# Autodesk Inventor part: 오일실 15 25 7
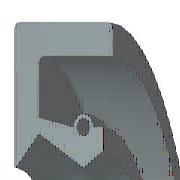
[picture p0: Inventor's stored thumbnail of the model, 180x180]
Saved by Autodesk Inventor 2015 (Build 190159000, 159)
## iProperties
Created: 2012-02
Part Number: 오일실 15 25 7
Material: 고무
Description: 오일-실
Document SubType Name: Modeling
Standard: KS B 2804
Designer: mduedu
Standards Organization: KS
Language: ko-KR
Size Designation: D - 15 25 7
Categories: <MemberInstance><Categories><Category DisplayName="샤프트 부품" InternalName="7f7aeb1f-a693-4053-b835-cee3144e0d98" Mnemonic="SHFT"><Category DisplayName="실링" Intern
Density: 0.93 g/cm^3
Appearance: 고무 - 검은색 - 버전 1.1
IsCustomPart: 1
Author: mduedu
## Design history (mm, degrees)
revolve "본체" stored, may be unused: angle "d17" = 90 deg
revolve "스프링1" stored, may be unused: angle "d18" = 90 deg
body "Solid1"
sketch "스케치1"
  geometry: L1 (0, 12.5)-(7, 12.5); L2 (7, 10.75)-(1.75, 10.75); L3 (1.75, 9.25)-(4.9, 7.5); L4 (4.9, 7.5)-(0, 7.5); L5 (0, 0)-(9.586, 0) reference; L6 (4.9, 7.5)-(6.3, 8.375); L7 (0, 18)-(0, -3) reference; L8 (-1.941, 0)-(11.507, 0) reference; L9 (4.2, 9.6)-(1.75, 10.09); L10 (1.75, 10.09)-(1.75, 10.75); L11 (0, 12.5)-(0, 7.588); L12 (4.9, 7.5)-(0, 7.5); L13 (1.75, 9.25)-(0.152, 7.528); L14 (7, 12.5)-(7, 10.75); L15 (5.6, 9.6)-(6.3, 9.6); L16 (6.3, 9.6)-(6.3, 8.375); C1 r 0.455 at (4.9, 9.6); A1 r 0.7 centre (4.9, 9.6) between (5.6, 9.6) and (4.2, 9.6); A2 r 0.088 centre (0.088, 7.588) between (0, 7.588) and (0.152, 7.528); 1 further point
  constraints: 28 end point, 5 horizontal alignment, 5 point on line, 4 point on circle, 4 vertical alignment, 3 centre point, 3 tangent, 2 collinear, 2 horizontal, 2 perpendicular, 1 coincident, 1 parallel
  dimensions: "d0" = 25 diameter of L1 L5 (= SD2); "d1" = 1.75 distance of L1.end L2.start (= SD); "d2" = 0.91 diameter of C1 (= SPDI); "d3" = 1.4 diameter of A1 (= SPDA); "d4" = 15 diameter of L3.end L5 (= NND); "d5" = 18.5 diameter of L3.start L5 (= TKDM); "d7" = 20.18 diameter of L9.end L5 (= TKDM + 0.24 x SWDT); "d8" = 1.75 distance between parallel lines of L11 L10 (= SD); "d9" = 4.9 distance from line of L11 C1.centre (= SPDST); "d10" = 19.2 diameter of C1.centre L5 (= HLDM); "d11" = 0.0875 radius of A2 (= 0.25 x LAB); "d12" = 6.3 distance between parallel lines of L11 L16 (= SDI); "d13" = 16.75 diameter of L6.end L5 (= ABDM); "d14" = 7 distance from line of L11 L1.end (= SWDT)
fillet "모깎기1" dims "d6" = 0.3 (= RR)
other parameters: "SD2" = 25 [user parameter; used in 1 equation term], "SWDT" = 7 [user parameter; used in 2 equation terms], "RR" = 0.3 [user parameter; used in 1 equation term], "SD" = 1.75 [user parameter; used in 2 equation terms], "NND" = 15 [user parameter; used in 1 equation term], "SPDA" = 1.4 [user parameter; used in 1 equation term], "SPDI" = 0.91 [user parameter; used in 1 equation term], "TKDM" = 18.5 [user parameter; used in 2 equation terms], "HLDM" = 19.2 [user parameter; used in 1 equation term], "ABDM" = 16.75 [user parameter; used in 1 equation term], "SDI" = 6.3 [user parameter; used in 1 equation term], "SPDST" = 4.9 [user parameter; used in 1 equation term], "LAB" = 0.35 [user parameter; used in 1 equation term], "d15" = 0, "d16" = 0, "d19" = 0
